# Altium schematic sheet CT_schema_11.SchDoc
size 389 x 278 mm
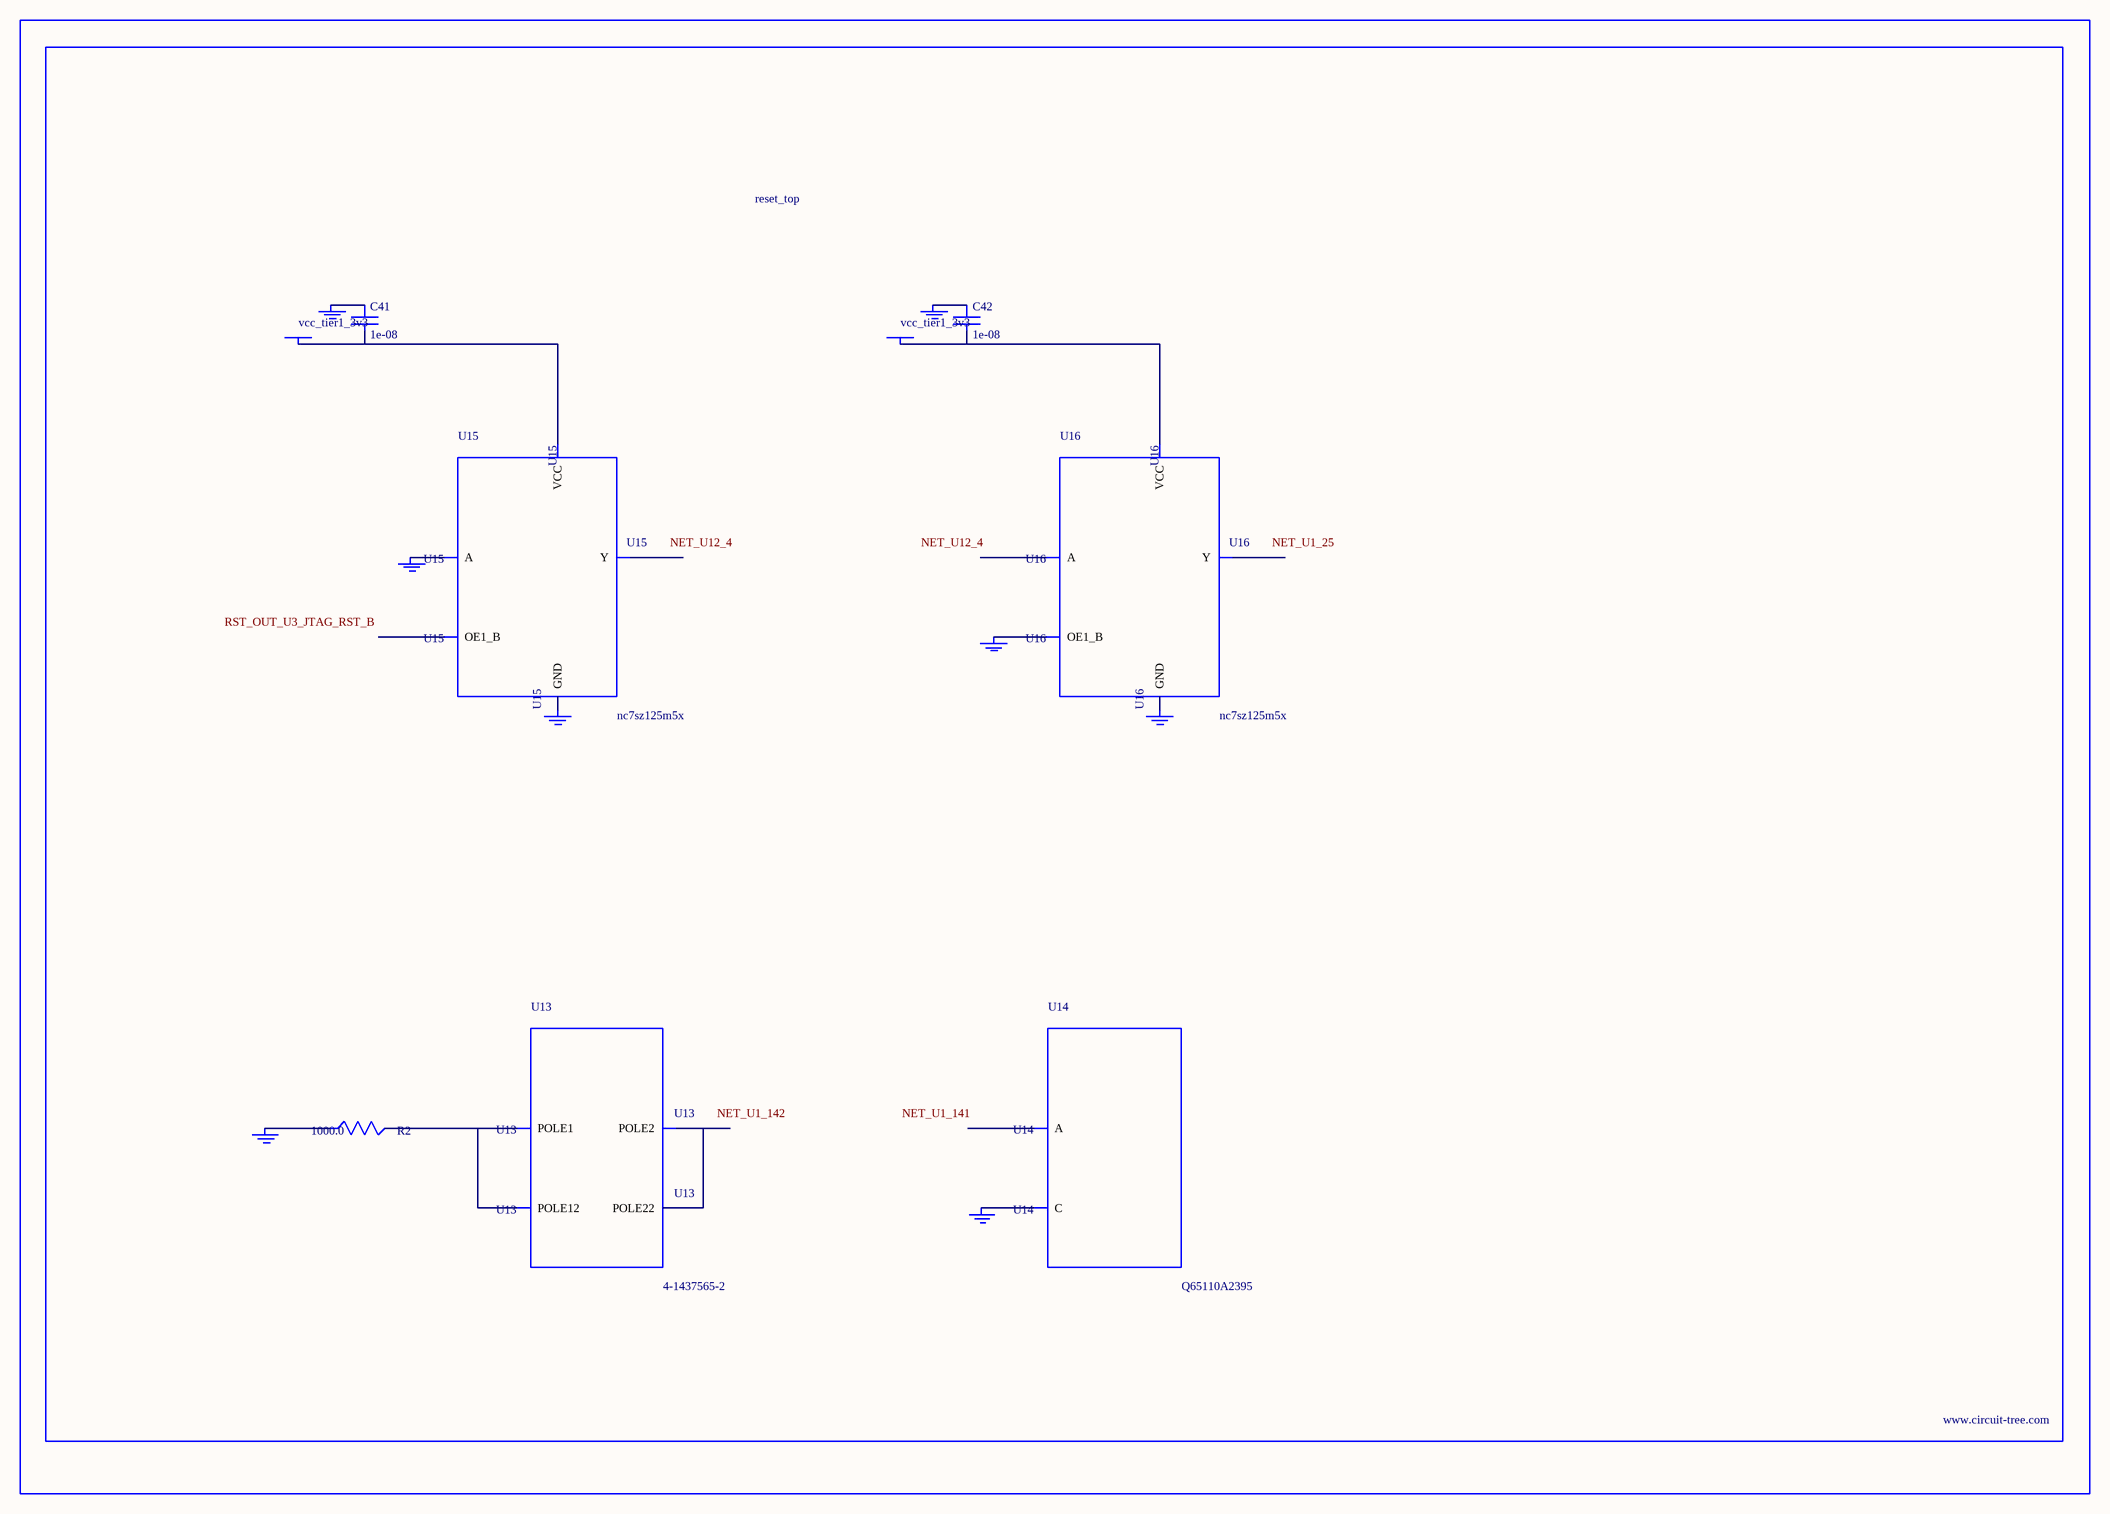
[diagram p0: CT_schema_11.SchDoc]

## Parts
BORDER10  (no value)
C41  1e-08  [C0402]
C42  1e-08  [C0402]
GND_INSTANCE_10_0  (no value)
GND_INSTANCE_10_1  (no value)
GND_INSTANCE_10_2  (no value)
GND_INSTANCE_10_3  (no value)
GND_INSTANCE_10_4  (no value)
GND_INSTANCE_10_5  (no value)
GND_INSTANCE_10_6  (no value)
GND_INSTANCE_10_7  (no value)
POWER_INSTANCE_10_0  vcc_tier1_3v3
POWER_INSTANCE_10_1  vcc_tier1_3v3
R2  1000.0  [R0603]
U13  4-1437565-2  [SW_4-1437565-2]
U14  Q65110A2395  [LGM67K-G1J2-24-Z]
U15  nc7sz125m5x  [NC7SZ125M5X]
U16  nc7sz125m5x  [NC7SZ125M5X]

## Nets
NetC41_1: C41.1 GND_INSTANCE_10_2.0(GND)
NetC41_2: C41.2 POWER_INSTANCE_10_0.0(PWR) U15.5(VCC)
NetC42_1: C42.1 GND_INSTANCE_10_5.0(GND)
NetC42_2: C42.2 POWER_INSTANCE_10_1.0(PWR) U16.5(VCC)
NetGND_INSTANCE_10_0_0: GND_INSTANCE_10_0.0(GND) R2.1
NetGND_INSTANCE_10_1_0: GND_INSTANCE_10_1.0(GND) U14.C
NetGND_INSTANCE_10_3_0: GND_INSTANCE_10_3.0(GND) U15.2(A)
NetGND_INSTANCE_10_4_0: GND_INSTANCE_10_4.0(GND) U15.3(GND)
NetGND_INSTANCE_10_6_0: GND_INSTANCE_10_6.0(GND) U16.1(OE1_B)
NetGND_INSTANCE_10_7_0: GND_INSTANCE_10_7.0(GND) U16.3(GND)
NetR2_2: R2.2 U13.1(POLE1) U13.2(POLE12)
NetU13_3: U13.3(POLE2) U13.4(POLE22)

Not connected (* = marked no-connect by the designer): U14 A; U15 1(OE1_B) 4(Y); U16 2(A) 4(Y)

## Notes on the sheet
- Labels drawn without touching a wire or pin: NET_U1_25, NET_U1_141, NET_U1_142, NET_U12_4, RST_OUT_U3_JTAG_RST_B

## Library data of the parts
BORDER10 = BORDER_PAGE10
C41 C42 = C0402C103K3RAC
GND_INSTANCE_10_0-GND_INSTANCE_10_7 = GND
POWER_INSTANCE_10_0 POWER_INSTANCE_10_1 = PWR
R2 = RC0603JR-071KL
